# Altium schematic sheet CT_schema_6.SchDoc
size 274 x 160 mm
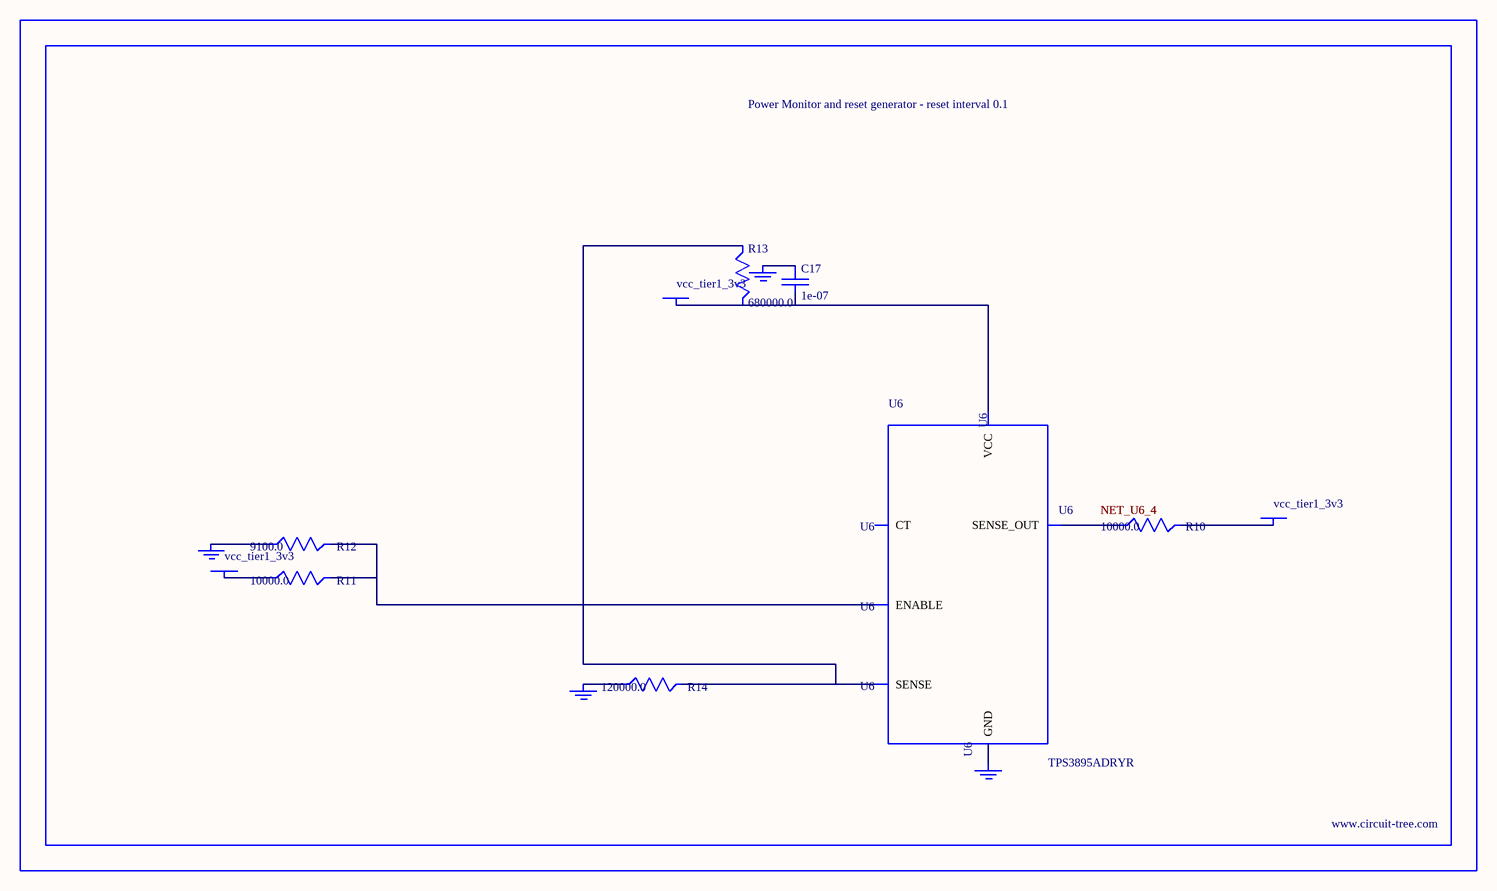
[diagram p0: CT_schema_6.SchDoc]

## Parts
BORDER5  (no value)
C17  1e-07  [C0402]
GND_INSTANCE_5_0  (no value)
GND_INSTANCE_5_1  (no value)
GND_INSTANCE_5_2  (no value)
GND_INSTANCE_5_3  (no value)
POWER_INSTANCE_5_0  vcc_tier1_3v3
POWER_INSTANCE_5_1  vcc_tier1_3v3
POWER_INSTANCE_5_2  vcc_tier1_3v3
R10  10000.0  [R0603]
R11  10000.0  [R0603]
R12  9100.0  [R0603]
R13  680000.0  [R0603]
R14  120000.0  [R0603]
U6  TPS3895ADRYR  [SON-6]

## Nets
NetC17_1: C17.1 GND_INSTANCE_5_2.0(GND)
NetC17_2: C17.2 POWER_INSTANCE_5_2.0(PWR) R13.2 U6.6(VCC)
NetGND_INSTANCE_5_0_0: GND_INSTANCE_5_0.0(GND) R12.1
NetGND_INSTANCE_5_1_0: GND_INSTANCE_5_1.0(GND) R14.1
NetGND_INSTANCE_5_3_0: GND_INSTANCE_5_3.0(GND) U6.2(GND)
NetPOWER_INSTANCE_5_0_0: POWER_INSTANCE_5_0.0(PWR) R11.1
NetPOWER_INSTANCE_5_1_0: POWER_INSTANCE_5_1.0(PWR) R10.2
NetR10_1: R10.1 U6.4(SENSE_OUT)
NetR11_2: R11.2 R12.2 U6.1(ENABLE)
NetR13_1: R13.1 R14.2 U6.3(SENSE)

Not connected (* = marked no-connect by the designer): U6 5(CT)

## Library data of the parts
BORDER5 = BORDER_PAGE5
C17 = C0402C104K3RACTU
GND_INSTANCE_5_0-GND_INSTANCE_5_3 = GND
POWER_INSTANCE_5_0-POWER_INSTANCE_5_2 = PWR
R10 R11 = RC0603JR-0710KL
R12 = RC0603JR-079K1L
R13 = RC0603JR-07680KL
R14 = RC0603JR-07120KL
